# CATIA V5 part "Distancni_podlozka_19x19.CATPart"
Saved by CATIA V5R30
Part number: Distancni_podlozka_19x19
Definition: EH 6281_19x19_3
Nomenclature: EH 6281_19x19_3
Source: Unknown
Description: PART--DESC
Bounding box of the stored display mesh (mm): x -139 to -120, y -27.99 to -9.01, z 20.7 to 39.7
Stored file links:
  E:\Bakalarka\Model\Forma_v7\Distancni_podlozka_19x19.CATPart
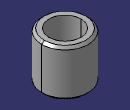
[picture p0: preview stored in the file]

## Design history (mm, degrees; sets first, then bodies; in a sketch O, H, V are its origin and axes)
Body1 "MANIFOLD_SOLID_BREP #3706" (main body)
  Solid1: solid without history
